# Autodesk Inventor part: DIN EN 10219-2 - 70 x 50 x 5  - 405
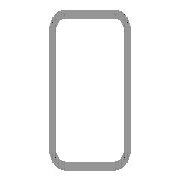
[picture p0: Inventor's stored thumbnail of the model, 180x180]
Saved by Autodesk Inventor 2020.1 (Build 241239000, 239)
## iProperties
Created: 2019-01
Part Number: DIN EN 10219-2 - 70 x 50 x 5  - 405
Material: Stahl, weich
Description: Kaltgeformte, geschweißte Baustahl-Hohlprofile aus unlegiertem Feinkorn-Baustahl
Document SubType Name: Modeling
Standard: DIN
Designer: lutzd
Standard Revision: 2006-07
Standards Organization: DIN
Language: de-DE
Size Designation: 70 x 50 x 5
Categories: <MemberInstance><Categories><Category DisplayName="Profile" InternalName="089c4875-fa83-4c05-b084-43b9cc11f5ed" Mnemonic="GRDR"><CategoryParameter DisplayName="
Stock Number: 70 x 50 x 5
Mass: 3289.77 g
Surface Area: 1699.12 cm^2
Volume: 419.079 cm^3
Density: 7.85 g/cm^3
Appearance: Halbpoliert
_CCFamilyMember: 17
_CCFamilyDisplayName: DIN EN 10219-2 (Rechteckiges Hohlprofil - Kaltgeformt) - Kaltgeformte, geschweißte Baustahl-Hohlprofile aus unlegiertem Feinkorn-Baustahl
_FrameMemberDoc: Frame Member File
_Version: 15.0.0
_GetPNFromCC: 1
G_L: 405,000 mm
G_W: 50,000 mm
G_H: 70,000 mm
DocNumber: ADSK-014149
Folder: .
Dimensions: 50x70x405 mm
Mass: 3,29 kg
+36A3EB15-949D-44DF-B236-94438D56E96E+SCHNITTDETAIL1: Schnittwinkel 90,00 grd
IsCustomPart: 1
Title: Profil-Bauteil
Author: lutzd
Revision Number: -
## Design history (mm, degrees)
node "Startebene"
node "Endebene"
sketch "Skizze"
  geometry: L1 (-25, -25)-(-25, 25); L2 (-15, 35)-(15, 35); L3 (25, 25)-(25, -25); L4 (15, -35)-(-15, -35); L5 (-15, 30)-(15, 30); L6 (20, 25)-(20, -25); L7 (15, -30)-(-15, -30); L8 (-20, -25)-(-20, 25); L9 (0, 51.899)-(0, -51.899) reference; L10 (-37.899, 0)-(37.899, 0) reference; A1 r 10 centre (-15, -25) between (-25, -25) and (-15, -35); A2 r 10 centre (-15, 25) between (-15, 35) and (-25, 25); A3 r 10 centre (15, 25) between (25, 25) and (15, 35); A4 r 10 centre (15, -25) between (15, -35) and (25, -25); A5 r 5 centre (-15, 25) between (-15, 30) and (-20, 25); A6 r 5 centre (15, 25) between (20, 25) and (15, 30); A7 r 5 centre (15, -25) between (15, -30) and (20, -25); A8 r 5 centre (-15, -25) between (-20, -25) and (-15, -30)
  constraints: 16 end point, 16 point on circle, 8 centre point, 8 tangent, 4 parallel, 3 equal radius, 2 perpendicular, 7 other
  dimensions: "d7" = 10 radius of A1 (= G_IR); "d10" = 70 distance between parallel lines of L2 L4 (= G_H); "d11" = 50 distance between parallel lines of L1 L3 (= G_W); "d12" = 5 distance between parallel lines of L3 L6 (= G_T); "d15" = 35 distance between parallel lines of L2 L10 (= 0.5 x d10); "d16" = 25 distance between parallel lines of L9 L3 (= 0.5 x d11)
extrude "Körper" new body sketch "Skizze" stored distance "d3" = 405 (= G_L); taper "d4" = 0 deg
node "Driven Length"
  sketch "Sketch3"
    geometry: L1 (0, 0)-(10, 0) reference
    constraints: 2 end point, 1 horizontal
  workplane "Work Plane3"
  sketch "Sketch4"
    geometry: L1 (-2, 50)-(12, 50) reference; L2 (-2, 455)-(12, 455) reference
    dimensions: "d18" = 405 distance between parallel lines of L1 L2 (derived)
workplane "Arbeitsebene4"
feature "Trennen1"
workplane "Arbeitsebene5"
feature "Trennen2"
sketch "Skizze5"
  geometry: L1 (0, -50)-(0, 0) reference; L2 (0, -25)-(183, -25); 3 further points
  constraints: 2 end point, 1 coincident, 1 horizontal, 1 midpoint, 1 point on line
  dimensions: "d19" = 68 distance of point (115, -25) point (183, -25); "d20" = 115 distance from line of point (115, -25) L1
hole "Bohrung1" sketch "Skizze5" at (183, -25), (115, -25) diameter "d21" = 6.647; stored, may be unused: countersink angle "d25" = 90 deg, drill point angle "d27" = 118 deg; dims "d22" = 16, "d23" = 4, "d24" = 2, "d26" = 8
body "Solid1"
other parameters: "G_W" = 50 [user parameter; used in 1 equation term], "G_H" = 70 [user parameter; used in 1 equation term], "G_T" = 5 [user parameter; used in 1 equation term], "G_IR" = 10 [user parameter; used in 1 equation term], "G_L" = 405 (= d18) [user parameter; used in 1 equation term], "G_OFFSET_END" = 0 [user parameter; used in 1 equation term], "d14" = 455 (= G_OFFSET_END + B_L), "B_L" = 455 [user parameter; used in 1 equation term], "d17" = 90 deg
